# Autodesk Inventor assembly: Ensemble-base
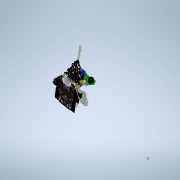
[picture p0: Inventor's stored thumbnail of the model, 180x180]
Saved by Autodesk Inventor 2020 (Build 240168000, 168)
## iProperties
Created: 2021-10
Part Number: Ensemble-base
Document SubType Name: Assembly
Designer: bruno
Mass: 78.0707 g
Surface Area: 663.807 cm^2
Volume: 70.3901 cm^3
Density: 1.10912 g/cm^3
Author: bruno
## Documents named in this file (12)
- C:\Users\bruno\OneDrive\Bureau\Robot-Inventor\Robot-equilibrage\Ensemble-base.iam
- C:\Users\bruno\OneDrive\Bureau\Robot-Inventor\Robot-equilibrage\base.ipt
- C:\Users\bruno\OneDrive\Bureau\Robot-Inventor\Robot-equilibrage\support-roue.ipt
- C:\Users\bruno\OneDrive\Bureau\Robot-Inventor\Robot-equilibrage\ecrou-hexa-2.ipt
- C:\Users\bruno\Documents\Inventor\Content Center Files\R2020\fr-FR\ANSI B18.6.7M(01)\ANSI B18.6.7M - M3x0,5 x 5(5).ipt
- C:\Users\bruno\OneDrive\Bureau\Robot-Inventor\Robot-equilibrage\pile.ipt
- C:\Users\bruno\OneDrive\Bureau\Robot-Inventor\Robot-equilibrage\microbit.ipt
- C:\Users\bruno\OneDrive\Bureau\Robot-Inventor\Robot-equilibrage\Ensemble-final.iam
- C:\Users\bruno\OneDrive\Bureau\Robot-Inventor\Robot-equilibrage\ecrou-hexa-3.ipt
- C:\Users\bruno\OneDrive\Bureau\Robot-Inventor\Robot-equilibrage\support-capteur.ipt
- C:\Users\bruno\OneDrive\Bureau\Robot-Inventor\Robot-equilibrage\capteur-ultrasons.ipt
- C:\Users\bruno\Documents\Inventor\Content Center Files\R2020\fr-FR\AS 1427(05)\AS 1427 - M3 x 5(5) II.ipt
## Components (19 placed, 11 different names)
1. base:1 — Placage:1, Placage:2, Placage:3, Placage:4, Placage:5, Placage:6, Placage:13, Placage:14, Placage:17, Placage:18, Placage:19, Affleurement:1, Logement:1, Logement:2, Logement:3
2. support-roue:1 — Placage:1, Placage:2, Affleurement:1
3. ecrou-hexa-2:1 — Placage:3, Placage:6, Placage:11
4. ecrou-hexa-2:2 — Placage:4, Placage:5, Placage:9, Placage:20
5. Vis à tête tronconique à empreinte cruciforme - Type IA - Métrique M3x0,5 x 5:1 — Placage:9, Tangente:1
6. Vis à tête tronconique à empreinte cruciforme - Type IA - Métrique M3x0,5 x 5:2 — Placage:11, Tangente:2
7. pile:1 — Placage:13, Placage:14
8. microbit:1 — Placage:17, Placage:18, Placage:19
9. Ensemble-final:1 [sub-assembly] — Placage:20, Tangente:1, Tangente:2
10. ecrou-hexa-3:1 — Logement:1, Logement:5
11. ecrou-hexa-3:2 — Logement:2
12. ecrou-hexa-3:3 — Logement:3, Logement:4
13. support-capteur:1 — Logement:4, Logement:5, Logement:6, Logement:7, Logement:8, Logement:9, Logement:10
14. capteur-ultrasons:1 — Logement:6, Logement:7, Logement:11, Logement:12
15. AS 1427 H - Métrique M3 x 5:1 — Logement:8
16. AS 1427 H - Métrique M3 x 5:2 — Logement:9
17. AS 1427 H - Métrique M3 x 5:3 — Logement:10
18. AS 1427 H - Métrique M3 x 5:4 — Logement:11
19. AS 1427 H - Métrique M3 x 5:5 — Logement:12
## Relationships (29: Mate 14, Insert 12, Tangent 2, Flush 1)
- Placage:1 [Mate]: base:1 ↔ support-roue:1
- Placage:2 [Mate]: base:1 ↔ support-roue:1
- Placage:3 [Mate]: base:1 ↔ ecrou-hexa-2:1
- Placage:4 [Mate]: base:1 ↔ ecrou-hexa-2:2
- Placage:5 [Mate]: base:1 ↔ ecrou-hexa-2:2
- Placage:6 [Mate]: base:1 ↔ ecrou-hexa-2:1
- Placage:9 [Mate]: ecrou-hexa-2:2 ↔ Vis à tête tronconique à empreinte cruciforme - Type IA - Métrique M3x0,5 x 5:1
- Placage:11 [Mate]: ecrou-hexa-2:1 ↔ Vis à tête tronconique à empreinte cruciforme - Type IA - Métrique M3x0,5 x 5:2
- Placage:13 [Mate]: base:1 ↔ pile:1
- Placage:14 [Mate]: base:1 ↔ pile:1
- Placage:17 [Mate]: base:1 ↔ microbit:1
- Placage:18 [Mate]: base:1 ↔ microbit:1
- Placage:19 [Mate]: base:1 ↔ microbit:1
- Affleurement:1 [Flush]: base:1 ↔ support-roue:1
- Logement:1 [Insert]: base:1 ↔ ecrou-hexa-3:1
- Logement:2 [Insert]: base:1 ↔ ecrou-hexa-3:2
- Logement:3 [Insert]: base:1 ↔ ecrou-hexa-3:3
- Logement:4 [Insert]: ecrou-hexa-3:3 ↔ support-capteur:1
- Logement:5 [Insert]: ecrou-hexa-3:1 ↔ support-capteur:1
- Logement:6 [Insert]: support-capteur:1 ↔ capteur-ultrasons:1
- Logement:7 [Insert]: support-capteur:1 ↔ capteur-ultrasons:1
- Logement:8 [Insert]: support-capteur:1 ↔ AS 1427 H - Métrique M3 x 5:1
- Logement:9 [Insert]: support-capteur:1 ↔ AS 1427 H - Métrique M3 x 5:2
- Logement:10 [Insert]: support-capteur:1 ↔ AS 1427 H - Métrique M3 x 5:3
- Logement:11 [Insert]: capteur-ultrasons:1 ↔ AS 1427 H - Métrique M3 x 5:4
- Logement:12 [Insert]: capteur-ultrasons:1 ↔ AS 1427 H - Métrique M3 x 5:5
- Placage:20 [Mate]: ecrou-hexa-2:2 ↔ Ensemble-final:1
- Tangente:1: Vis à tête tronconique à empreinte cruciforme - Type IA - Métrique M3x0,5 x 5:1 ↔ Ensemble-final:1
- Tangente:2: Vis à tête tronconique à empreinte cruciforme - Type IA - Métrique M3x0,5 x 5:2 ↔ Ensemble-final:1
